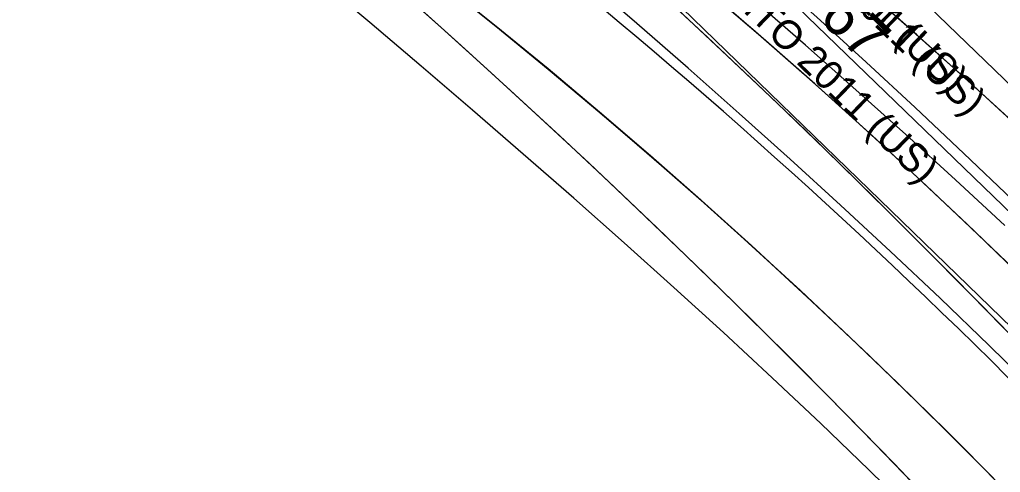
# Model space of a CAD drawing. Extents: x 916040 to 917457, y 328936 to 330267.
# Drawn here: x 916503.03 to 916551.21, y 329971.77 to 329994 of the extents above; entities that cross this region are included whole.
import ezdxf

# ---------------------------------------------------------------- set-up
doc = ezdxf.new("R2010")
doc.units = 0
for name, color, linetype in [('EB_LeftontoManchester_WB67', 7, 'Continuous'), ('EB_LeftontoManchester_WB67_v2', 7, 'Continuous'), ('NB_ThruontoManchester_WB67', 7, 'Continuous'), ('SB_LeftontoRoute25_WB67', 7, 'Continuous'), ('SB_RightontoRoute25_WB67_v2', 7, 'Continuous'), ('SB_ThruontonSacoRd_WB67', 7, 'Continuous'), ('WB_RightontoManchester_WB67', 7, 'Continuous')]:
    doc.layers.add(name, color=color, linetype=linetype)

msp = doc.modelspace()

# ---------------------------------------------------------------- linework, layer by layer
at = {"layer": 'EB_LeftontoManchester_WB67'}
msp.add_line((916521.487, 330013.732), (916559.587, 329976.89), dxfattribs=at)
msp.add_lwpolyline([(916551.793, 329989.013), (916549.355, 329991.239), (916546.898, 329993.444), (916544.423, 329995.627), (916541.929, 329997.789), (916539.416, 329999.93), (916536.885, 330002.049), (916534.336, 330004.146), (916531.769, 330006.221), (916529.184, 330008.274), (916526.581, 330010.305), (916523.962, 330012.313), (916521.325, 330014.299), (916518.671, 330016.262), (916516, 330018.202), (916513.313, 330020.119), (916510.609, 330022.013), (916508.707, 330023.325)], dxfattribs=at)
msp.add_arc((916291.649, 329706.552), 388, 12.26429, 55.55708, dxfattribs=at)
at = {"layer": 'EB_LeftontoManchester_WB67_v2'}
msp.add_line((916521.487, 330013.732), (916559.587, 329976.89), dxfattribs=at)
msp.add_lwpolyline([(916551.989, 329988.832), (916549.556, 329991.057), (916547.103, 329993.261), (916544.632, 329995.444), (916542.142, 329997.605), (916539.634, 329999.746), (916537.108, 330001.864), (916534.563, 330003.961), (916532, 330006.035), (916529.42, 330008.088), (916526.822, 330010.119), (916524.207, 330012.127), (916521.575, 330014.112), (916518.925, 330016.075), (916516.259, 330018.015), (916513.577, 330019.932), (916510.878, 330021.826), (916508.707, 330023.325)], dxfattribs=at)
msp.add_arc((916291.649, 329706.552), 388, 12.26429, 55.55708, dxfattribs=at)
at = {"layer": 'NB_ThruontoManchester_WB67'}
for points in [[(916501.321, 330027.35), (916503.973, 330025.378), (916506.614, 330023.395), (916509.243, 330021.399), (916511.861, 330019.391), (916514.466, 330017.369), (916517.058, 330015.333), (916519.637, 330013.282), (916522.202, 330011.217), (916524.753, 330009.136), (916527.29, 330007.04), (916529.812, 330004.929), (916532.319, 330002.801), (916534.811, 330000.656), (916537.287, 329998.495), (916539.746, 329996.318), (916542.19, 329994.123), (916544.617, 329991.911), (916547.027, 329989.682), (916549.419, 329987.436), (916551.795, 329985.172)], [(916508.833, 330023.233), (916511.568, 330021.341), (916514.283, 330019.427), (916516.979, 330017.491), (916519.655, 330015.534), (916522.313, 330013.555), (916524.952, 330011.555), (916527.573, 330009.533), (916530.175, 330007.489), (916532.758, 330005.424), (916535.323, 330003.337), (916537.869, 330001.228), (916540.396, 329999.098), (916542.904, 329996.947), (916545.394, 329994.774), (916547.864, 329992.581), (916550.315, 329990.366), (916552.746, 329988.131)]]:
    msp.add_lwpolyline(points, dxfattribs=at)
msp.add_arc((916291.649, 329706.552), 388, 11.6689, 55.55708, dxfattribs=at)
at = {"layer": 'SB_LeftontoRoute25_WB67'}
for points in [[(916502.341, 330022.84), (916504.943, 330020.735), (916507.539, 330018.621), (916510.128, 330016.497), (916512.708, 330014.361), (916515.279, 330012.213), (916517.834, 330010.055), (916520.377, 330007.884), (916522.909, 330005.697), (916525.427, 330003.494), (916527.931, 330001.276), (916530.42, 329999.041), (916532.894, 329996.789), (916535.353, 329994.519), (916537.795, 329992.232), (916540.22, 329989.927), (916542.628, 329987.604), (916545.019, 329985.263), (916547.391, 329982.903), (916549.745, 329980.526), (916552.08, 329978.13), (916554.396, 329975.715), (916556.693, 329973.282), (916558.969, 329970.83)], [(916502.58, 330020.867), (916505.303, 330018.983), (916508.039, 330017.116), (916510.791, 330015.257), (916513.545, 330013.365), (916516.283, 330011.439), (916519.005, 330009.478), (916521.709, 330007.484), (916524.394, 330005.457), (916527.059, 330003.399), (916529.704, 330001.309), (916532.327, 329999.188), (916534.929, 329997.037), (916537.508, 329994.856), (916540.063, 329992.646), (916542.595, 329990.406), (916545.103, 329988.138), (916547.586, 329985.841), (916550.044, 329983.516), (916552.477, 329981.164), (916554.883, 329978.784), (916557.264, 329976.378), (916559.617, 329973.944), (916561.944, 329971.485)], [(916500.579, 330012.528), (916503.356, 330010.63), (916506.139, 330008.75), (916508.896, 330006.855), (916511.626, 330004.934), (916514.329, 330002.986), (916517.006, 330001.012), (916519.658, 329999.01), (916522.284, 329996.981), (916524.884, 329994.925), (916527.459, 329992.841), (916530.01, 329990.73), (916532.534, 329988.592), (916535.034, 329986.427), (916537.508, 329984.235), (916539.957, 329982.016), (916542.38, 329979.77), (916544.777, 329977.498), (916547.149, 329975.2), (916549.494, 329972.876), (916551.812, 329970.526)], [(916502.162, 330012.039), (916504.724, 330009.936), (916507.275, 330007.824), (916509.814, 330005.703), (916512.335, 330003.574), (916514.842, 330001.433), (916517.334, 329999.28), (916519.812, 329997.112), (916522.275, 329994.93), (916524.722, 329992.733), (916527.153, 329990.521), (916529.567, 329988.292), (916531.964, 329986.047), (916534.344, 329983.785), (916536.706, 329981.506), (916539.05, 329979.211), (916541.376, 329976.898), (916543.683, 329974.567), (916545.972, 329972.219), (916548.241, 329969.853)]]:
    msp.add_lwpolyline(points, dxfattribs=at)
msp.add_arc((916339.95, 329763.805), 300, 42.35327, 56.08067, dxfattribs=at)
at = {"layer": 'SB_RightontoRoute25_WB67_v2'}
for points in [[(916501.298, 330023.68), (916503.903, 330021.578), (916506.502, 330019.468), (916509.094, 330017.348), (916511.677, 330015.217), (916514.252, 330013.074), (916516.813, 330010.92), (916519.362, 330008.754), (916521.898, 330006.573), (916524.421, 330004.377), (916526.931, 330002.165), (916529.426, 329999.937), (916531.906, 329997.691), (916534.371, 329995.429), (916536.82, 329993.149), (916539.252, 329990.851), (916541.667, 329988.535), (916544.065, 329986.202), (916546.444, 329983.849), (916548.806, 329981.479), (916551.148, 329979.09), (916553.472, 329976.683)], [(916501.494, 330021.626), (916504.212, 330019.735), (916506.943, 330017.86), (916509.686, 330016.004), (916512.445, 330014.126), (916515.19, 330012.213), (916517.918, 330010.266), (916520.629, 330008.285), (916523.322, 330006.272), (916525.995, 330004.226), (916528.648, 330002.149), (916531.28, 330000.04), (916533.891, 329997.901), (916536.479, 329995.732), (916539.044, 329993.534), (916541.585, 329991.306), (916544.103, 329989.049), (916546.596, 329986.763), (916549.064, 329984.45), (916551.507, 329982.108)], [(916501.134, 330012.877), (916503.7, 330010.778), (916506.256, 330008.67), (916508.8, 330006.553), (916511.328, 330004.427), (916513.84, 330002.291), (916516.339, 330000.143), (916518.823, 329997.981), (916521.292, 329995.805), (916523.745, 329993.614), (916526.182, 329991.408), (916528.603, 329989.185), (916531.007, 329986.947), (916533.394, 329984.692), (916535.764, 329982.42), (916538.115, 329980.131), (916540.448, 329977.825), (916542.763, 329975.501), (916545.059, 329973.16), (916547.335, 329970.802)], [(916502.244, 330011.387), (916505.029, 330009.5), (916507.797, 330007.616), (916510.537, 330005.706), (916513.251, 330003.769), (916515.939, 330001.805), (916518.6, 329999.814), (916521.236, 329997.796), (916523.847, 329995.751), (916526.432, 329993.678), (916528.993, 329991.578), (916531.528, 329989.451), (916534.037, 329987.296), (916536.522, 329985.115), (916538.981, 329982.906), (916541.414, 329980.671), (916543.822, 329978.41), (916546.203, 329976.122), (916548.559, 329973.809), (916550.888, 329971.469)]]:
    msp.add_lwpolyline(points, dxfattribs=at)
msp.add_arc((916339.95, 329763.805), 300, 42.35327, 56.08067, dxfattribs=at)
at = {"layer": 'SB_ThruontonSacoRd_WB67'}
for points in [[(916552.014, 329981.616), (916549.575, 329983.964), (916547.11, 329986.284), (916544.619, 329988.578), (916542.103, 329990.843), (916539.561, 329993.081), (916536.995, 329995.29), (916534.404, 329997.471), (916531.788, 329999.623), (916529.149, 330001.745), (916526.486, 330003.839), (916523.8, 330005.902), (916521.092, 330007.936), (916518.36, 330009.939), (916515.606, 330011.911), (916512.831, 330013.853), (916510.034, 330015.764), (916507.248, 330017.651), (916504.482, 330019.549), (916501.733, 330021.46)], [(916557.762, 329970.902), (916555.423, 329973.29), (916553.058, 329975.656), (916550.667, 329977.998), (916548.252, 329980.319), (916545.815, 329982.617), (916543.356, 329984.895), (916540.879, 329987.152), (916538.384, 329989.391), (916535.874, 329991.612), (916533.35, 329993.818), (916530.814, 329996.008), (916528.268, 329998.185), (916525.714, 330000.35), (916523.152, 330002.505), (916520.584, 330004.651), (916518.012, 330006.788), (916515.437, 330008.92), (916512.86, 330011.046), (916510.282, 330013.169), (916507.705, 330015.289), (916505.129, 330017.407), (916502.554, 330019.525)], [(916550.863, 329971.494), (916548.533, 329973.834), (916546.178, 329976.147), (916543.797, 329978.434), (916541.391, 329980.694), (916538.961, 329982.927), (916536.505, 329985.132), (916534.026, 329987.309), (916531.522, 329989.459), (916528.995, 329991.58), (916526.445, 329993.673), (916523.871, 329995.737), (916521.275, 329997.773), (916518.656, 329999.779), (916516.015, 330001.756), (916513.352, 330003.704), (916510.668, 330005.621), (916507.963, 330007.509), (916505.236, 330009.366), (916502.492, 330011.22)], [(916547.075, 329969.618), (916544.745, 329971.901), (916542.389, 329974.164), (916540.008, 329976.409), (916537.603, 329978.637), (916535.176, 329980.849), (916532.728, 329983.047), (916530.26, 329985.23), (916527.775, 329987.402), (916525.273, 329989.562), (916522.758, 329991.713), (916520.23, 329993.856), (916517.69, 329995.991), (916515.142, 329998.121), (916512.585, 330000.246), (916510.022, 330002.368), (916507.453, 330004.487), (916504.881, 330006.605), (916502.306, 330008.723)]]:
    msp.add_lwpolyline(points, dxfattribs=at)
msp.add_arc((916339.95, 329763.805), 300, 42.35327, 56.08067, dxfattribs=at)
at = {"layer": 'WB_RightontoManchester_WB67'}
for p, q in [((916563.187, 329979.644), (916525.133, 330016.535)), ((916519.217, 330010.432), (916557.271, 329973.541))]:
    msp.add_line(p, q, dxfattribs=at)
msp.add_lwpolyline([(916551.433, 329983.888), (916549.014, 329986.134), (916546.576, 329988.359), (916544.119, 329990.563), (916541.643, 329992.745), (916539.147, 329994.905), (916536.633, 329997.044), (916534.101, 329999.161), (916531.55, 330001.256), (916528.981, 330003.329), (916526.395, 330005.379), (916523.79, 330007.407), (916521.168, 330009.412), (916518.529, 330011.394), (916515.873, 330013.353), (916513.199, 330015.289), (916510.509, 330017.202), (916507.803, 330019.091), (916506.443, 330020.027)], dxfattribs=at)
msp.add_arc((916291.649, 329706.552), 384, 12.55823, 55.55708, dxfattribs=at)

# ---------------------------------------------------------------- texts
at = {"layer": 'EB_LeftontoManchester_WB67'}
msp.add_text('AASHTO 2011 (US)', height=1.41667, rotation=315.9623, dxfattribs=at).set_placement((916537.468, 330000.988))
at = {"layer": 'EB_LeftontoManchester_WB67_v2'}
msp.add_text('AASHTO 2011 (US)', height=1.41667, rotation=315.9623, dxfattribs=at).set_placement((916536.572, 330002.092))
at = {"layer": 'WB_RightontoManchester_WB67'}
for s, height, p in [('WB-67', 2.125, (916538.259, 329997.89)), ('AASHTO 2011 (US)', 1.41667, (916535.182, 329997.667))]:
    msp.add_text(s, height=height, rotation=315.8895, dxfattribs=at).set_placement(p)

doc.saveas('drawing.dxf')
